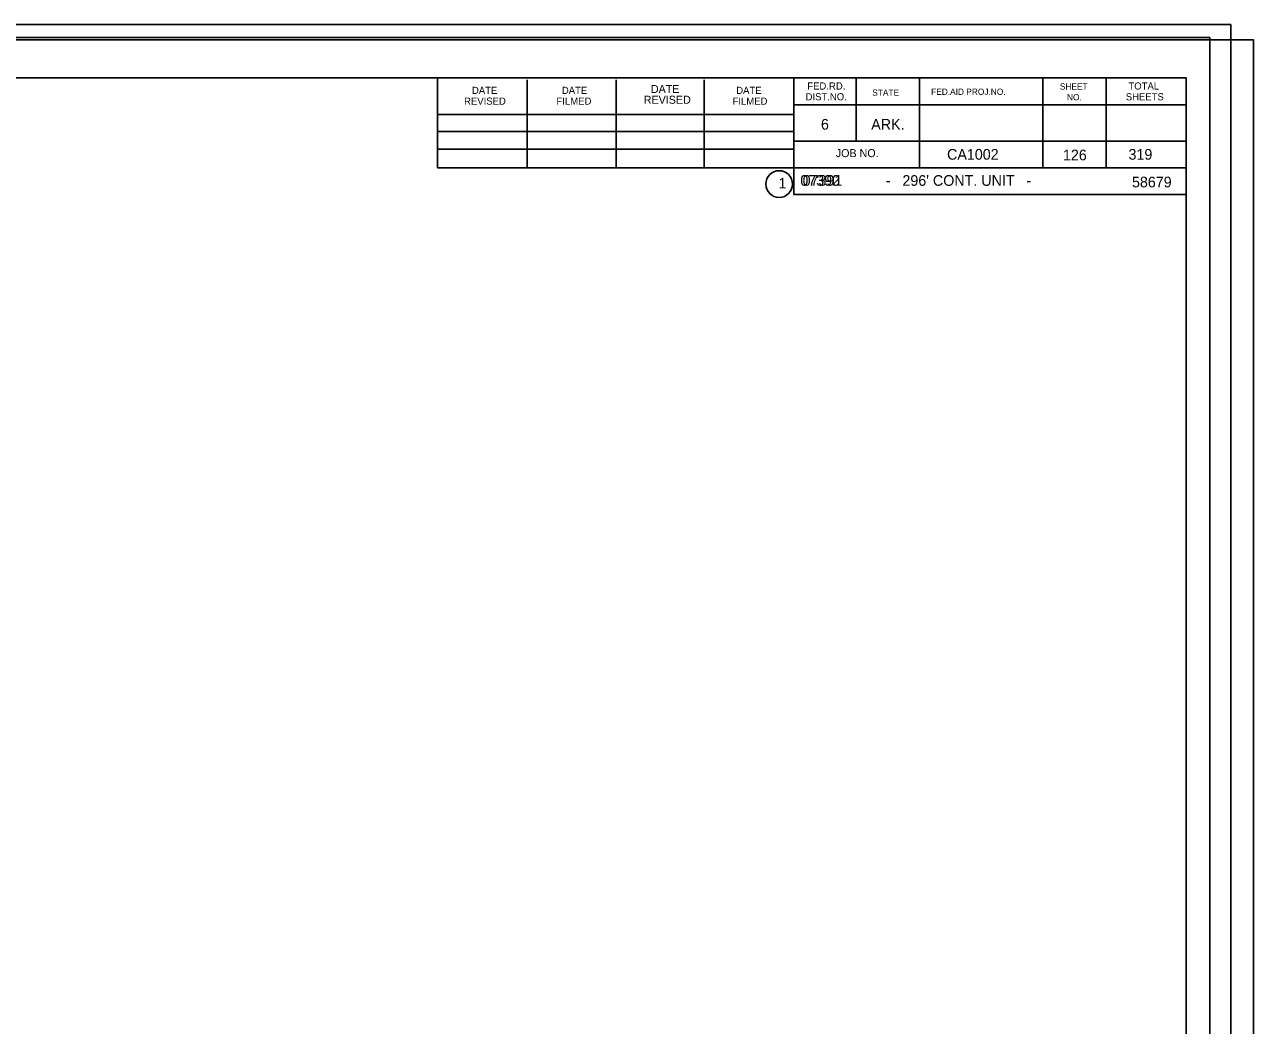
# Model space of a CAD drawing. Extents: x -1771525.9 to -1771483.9, y -422628.9 to -422606.9.
# Drawn here: x -1771504.92 to -1771491.42, y -422617.89 to -422606.91 of the extents above; entities that cross this region are included whole.
import ezdxf

# ---------------------------------------------------------------- set-up
doc = ezdxf.new("R2010")
doc.units = 0
for name, color, linetype in [('border', 7, 'Continuous'), ('Border 2660-Hwy18 - Level 62', 7, 'Continuous'), ('Border 2660-Hwy18 - Level 63', 7, 'Continuous'), ('Border 2660-Hwy18 - Text', 7, 'Continuous'), ('Bridge No BLFR', 7, 'Continuous'), ('Bridge No BLO', 7, 'Continuous'), ('Bridge No Ditch 81', 7, 'Continuous'), ('Level 62 PDF', 7, 'Continuous'), ('Text', 7, 'Continuous'), ('Title Text', 7, 'Continuous')]:
    doc.layers.add(name, color=color, linetype=linetype)

msp = doc.modelspace()

# ---------------------------------------------------------------- linework, layer by layer
at = {"layer": 'border'}
for p, q in [((-1771524.168, -422607.492), (-1771492.157, -422607.492)), ((-1771500.383, -422608.48), (-1771500.383, -422607.492)), ((-1771499.398, -422608.48), (-1771499.398, -422607.512)), ((-1771498.421, -422608.48), (-1771498.421, -422607.512)), ((-1771497.454, -422608.48), (-1771497.454, -422607.512)), ((-1771496.468, -422607.492), (-1771496.468, -422608.772)), ((-1771495.784, -422607.492), (-1771495.784, -422608.186)), ((-1771495.089, -422607.492), (-1771495.089, -422608.48)), ((-1771493.732, -422607.492), (-1771493.732, -422608.48)), ((-1771493.037, -422607.492), (-1771493.037, -422608.48)), ((-1771492.157, -422628.038), (-1771492.157, -422607.492)), ((-1771492.157, -422607.786), (-1771496.468, -422607.786)), ((-1771492.157, -422607.784), (-1771492.157, -422607.784)), ((-1771500.383, -422607.894), (-1771496.468, -422607.894)), ((-1771500.383, -422608.08), (-1771496.468, -422608.08)), ((-1771500.383, -422608.48), (-1771500.383, -422608.274)), ((-1771500.383, -422608.274), (-1771496.468, -422608.274)), ((-1771492.157, -422608.186), (-1771496.468, -422608.186)), ((-1771496.171, -422608.186), (-1771492.157, -422608.186)), ((-1771492.157, -422608.48), (-1771500.383, -422608.48)), ((-1771496.468, -422608.772), (-1771492.157, -422608.772))]:
    msp.add_line(p, q, dxfattribs=at)
msp.add_circle((-1771496.629, -422608.658), 0.147, dxfattribs=at)
at = {"layer": 'Border 2660-Hwy18 - Level 62'}
msp.add_lwpolyline([(-1771525.789, -422606.907), (-1771491.67, -422606.907), (-1771491.67, -422628.716), (-1771525.789, -422628.716)], close=True, dxfattribs=at)
at = {"layer": 'Border 2660-Hwy18 - Level 63'}
msp.add_lwpolyline([(-1771525.9, -422607.05), (-1771491.9, -422607.05), (-1771491.9, -422628.419), (-1771525.9, -422628.419)], close=True, dxfattribs=at)
at = {"layer": 'Level 62 PDF'}
msp.add_lwpolyline([(-1771525.539, -422607.073), (-1771491.42, -422607.073), (-1771491.42, -422628.883), (-1771525.539, -422628.883)], close=True, dxfattribs=at)

# ---------------------------------------------------------------- texts
at = {"layer": 'Border 2660-Hwy18 - Text'}
for s, height, p in [('DATE', 0.0782, (-1771500.003, -422607.668)), ('DATE', 0.0782, (-1771499.016, -422607.668)), ('DATE', 0.0879, (-1771498.038, -422607.658)), ('DATE', 0.0782, (-1771497.101, -422607.668)), ('FED.RD.', 0.0782, (-1771496.32, -422607.62)), ('SHEET', 0.0684, (-1771493.546, -422607.62)), ('TOTAL', 0.0782, (-1771492.793, -422607.62)), ('REVISED', 0.0782, (-1771500.09, -422607.786)), ('FILMED', 0.0782, (-1771499.075, -422607.786)), ('REVISED', 0.0879, (-1771498.116, -422607.776)), ('FILMED', 0.0782, (-1771497.141, -422607.786)), ('DIST.NO.', 0.0782, (-1771496.339, -422607.738)), ('STATE', 0.0684, (-1771495.607, -422607.688)), ('FED.AID PROJ.NO.', 0.06839, (-1771494.96, -422607.678)), ('NO.', 0.0684, (-1771493.468, -422607.738)), ('SHEETS', 0.0782, (-1771492.822, -422607.738)), ('6', 0.117, (-1771496.17, -422608.06)), ('ARK.', 0.1172, (-1771495.618, -422608.06)), ('JOB NO.', 0.0879, (-1771496.007, -422608.362)), ('CA1002', 0.1172, (-1771494.785, -422608.39)), ('319', 0.1172, (-1771492.792, -422608.39)), ('1', 0.117, (-1771496.636, -422608.706))]:
    msp.add_text(s, height=height, dxfattribs=at).set_placement(p)
at = {"layer": 'Bridge No BLFR'}
msp.add_text('07392', height=0.1172, dxfattribs=at).set_placement((-1771496.397, -422608.676))
at = {"layer": 'Bridge No BLO'}
msp.add_text('07391', height=0.1172, dxfattribs=at).set_placement((-1771496.371, -422608.676))
at = {"layer": 'Bridge No Ditch 81'}
msp.add_text('07390', height=0.1172, dxfattribs=at).set_placement((-1771496.396, -422608.676))
at = {"layer": 'Text'}
msp.add_text('126', height=0.1172, dxfattribs=at).set_placement((-1771493.512, -422608.397))
at = {"layer": 'Title Text'}
for s, height, p in [("-   296' CONT. UNIT   -", 0.11722, (-1771495.458, -422608.677)), ('58679', 0.1172, (-1771492.754, -422608.694))]:
    msp.add_text(s, height=height, dxfattribs=at).set_placement(p)

doc.saveas('drawing.dxf')
